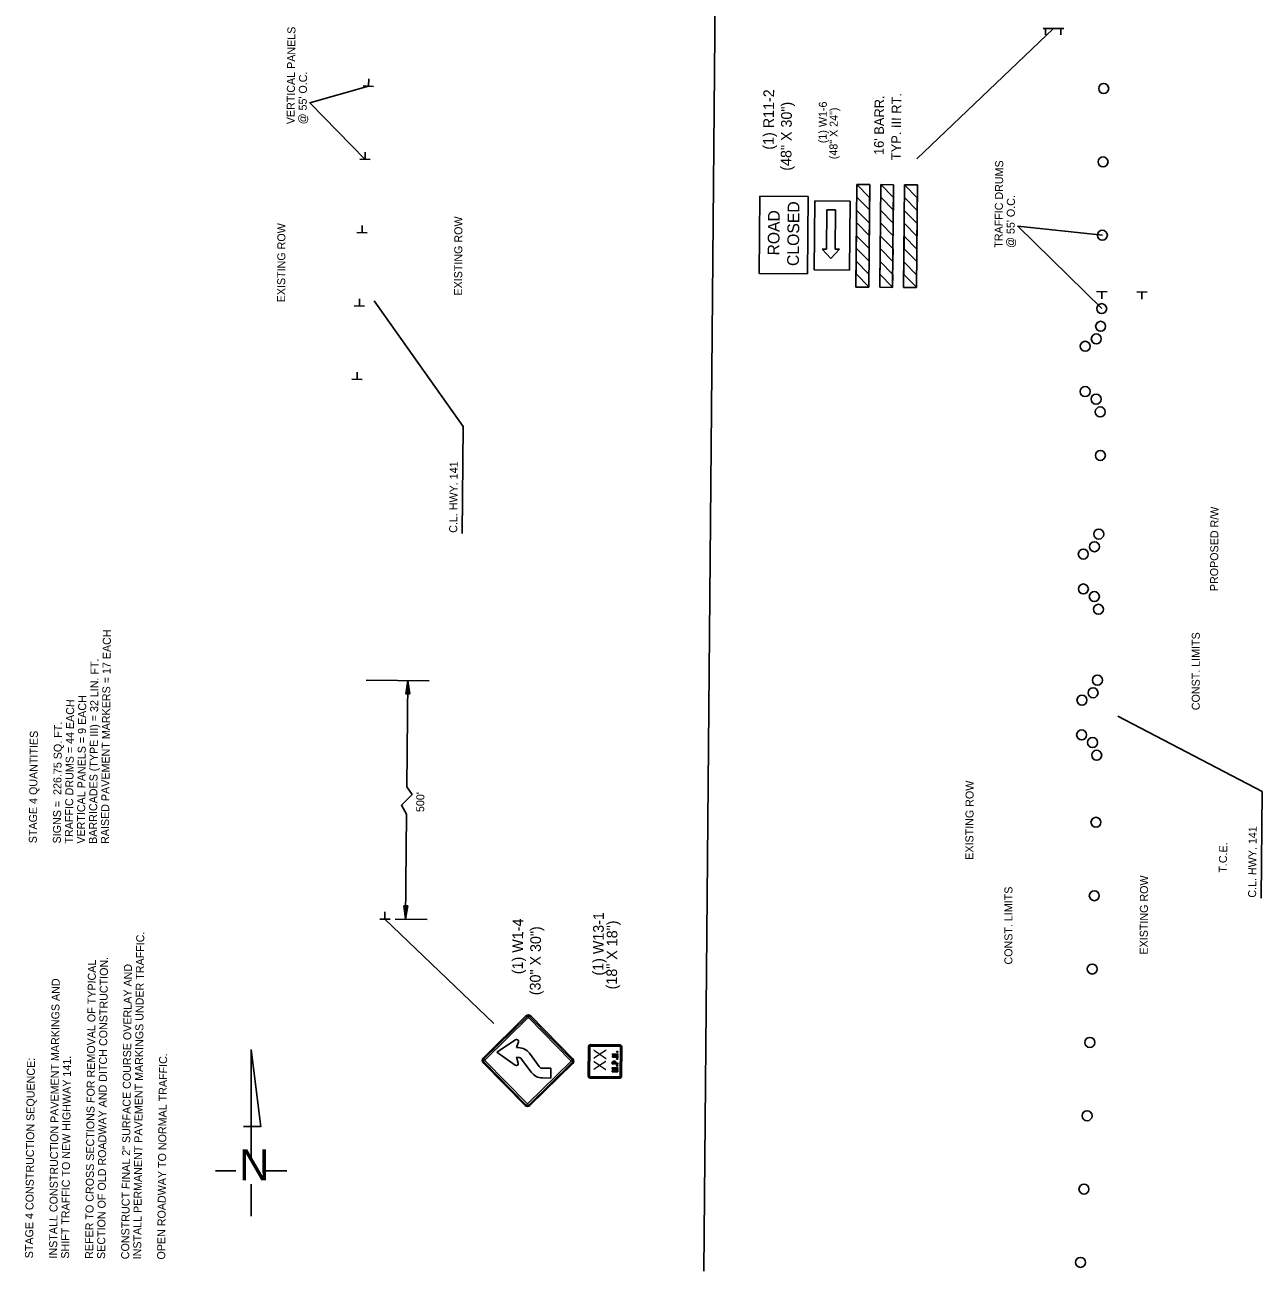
# Model space of a CAD drawing. Extents: x 1770269 to 1771406, y 724066 to 730989.
# Drawn here: x 1770269 to 1771196, y 729408 to 730342 of the extents above; entities that cross this region are included whole.
import ezdxf

# ---------------------------------------------------------------- set-up
doc = ezdxf.new("R2010")
doc.units = 0
for name, color, linetype in [('Default', 7, 'Continuous'), ('E_Existing ROW', 7, 'Continuous'), ('R_Border Notes', 7, 'Continuous'), ('R_Border PE', 7, 'Continuous'), ('R_Dimension', 7, 'Continuous'), ('R_Draft', 7, 'Continuous'), ('R_Horz Alg Annot', 7, 'Continuous'), ('R_MOT', 7, 'Continuous'), ('R_ROW Annot', 7, 'Continuous'), ('R_Temp Easement Annot', 7, 'Continuous'), ('Roadway-Signs', 7, 'Continuous')]:
    doc.layers.add(name, color=color, linetype=linetype)

msp = doc.modelspace()

# ---------------------------------------------------------------- linework, layer by layer
at = {"layer": 'Default'}
for p, q in [((1770529.9, 730295.6), (1770522.08, 730295.95)), ((1770526.02, 730295.89), (1770526.26, 730301.23)), ((1770527.4, 730240.68), (1770519.58, 730240.99)), ((1770523.52, 730240.95), (1770523.73, 730246.28)), ((1770525.16, 730185.74), (1770517.34, 730186.01)), ((1770521.28, 730185.99), (1770521.46, 730191.33)), ((1770519.3, 730131.03), (1770519.46, 730136.37)), ((1771079.54, 730141.71), (1771071.71, 730141.78)), ((1771075.64, 730141.63), (1771075.6, 730136.29)), ((1771109.53, 730141.44), (1771101.71, 730141.51)), ((1771105.64, 730141.36), (1771105.59, 730136.02)), ((1770523.19, 730130.8), (1770515.37, 730131.03)), ((1770530.42, 730134.89), (1770597.04, 730040.58)), ((1770517.59, 730076.06), (1770517.72, 730081.39)), ((1770521.48, 730075.84), (1770513.66, 730076.04)), ((1770596.31, 729960.58), (1770597.04, 730040.58)), ((1771087.61, 729823.56), (1771195.68, 729767.17)), ((1771194.95, 729687.17), (1771195.68, 729767.17)), ((1770542.3, 729671.47), (1770534.48, 729671.54)), ((1770538.41, 729671.62), (1770538.46, 729676.96))]:
    msp.add_line(p, q, dxfattribs=at)
at = {"layer": 'R_Border Notes'}
msp.add_line((1770791.68, 730988.54), (1770777.32, 729407.71), dxfattribs=at)
at = {"layer": 'R_Border PE'}
for p, q in [((1770936.97, 730241.15), (1771039.33, 730338.97)), ((1770619.95, 729593.31), (1770538.39, 729671.51))]:
    msp.add_line(p, q, dxfattribs=at)
at = {"layer": 'R_Dimension'}
for p, q in [((1770524.31, 729850.6), (1770571.58, 729850.17)), ((1770553.99, 729840.33), (1770555.58, 729850.32)), ((1770554.24, 729840.33), (1770555.57, 729848.65)), ((1770554.5, 729840.33), (1770555.55, 729846.93)), ((1770554.86, 729770.7), (1770555.58, 729850.32)), ((1770556.49, 729840.31), (1770555.55, 729846.93)), ((1770556.74, 729840.3), (1770555.57, 729848.65)), ((1770556.99, 729840.3), (1770555.58, 729850.32)), ((1770553.99, 729840.33), (1770556.99, 729840.3)), ((1770554.75, 729840.32), (1770555.54, 729845.26)), ((1770555.01, 729840.32), (1770555.52, 729843.57)), ((1770555.26, 729840.32), (1770555.51, 729841.9)), ((1770555.73, 729840.31), (1770555.51, 729841.9)), ((1770555.98, 729840.31), (1770555.52, 729843.57)), ((1770556.24, 729840.31), (1770555.54, 729845.26)), ((1770553.95, 729671.37), (1770554.67, 729750.19)), ((1770552.54, 729681.38), (1770553.95, 729671.37)), ((1770555.54, 729681.35), (1770552.54, 729681.38)), ((1770552.79, 729681.38), (1770553.97, 729673.04)), ((1770553.05, 729681.38), (1770553.98, 729674.76)), ((1770553.3, 729681.37), (1770554, 729676.42)), ((1770553.55, 729681.37), (1770554.01, 729678.12)), ((1770553.81, 729681.37), (1770554.03, 729679.79)), ((1770555.54, 729681.35), (1770553.95, 729671.37)), ((1770555.29, 729681.35), (1770553.97, 729673.04)), ((1770555.04, 729681.36), (1770553.98, 729674.76)), ((1770554.79, 729681.36), (1770554, 729676.42)), ((1770554.53, 729681.36), (1770554.01, 729678.12)), ((1770554.28, 729681.36), (1770554.03, 729679.79)), ((1770546.09, 729671.44), (1770569.95, 729671.22))]:
    msp.add_line(p, q, dxfattribs=at)
for points in [[(1770523.49, 730240.83), (1770482.16, 730283.36), (1770525.99, 730295.78)], [(1771075.51, 730128.99), (1771012.61, 730190.77), (1771076.01, 730183.99)], [(1770554.67, 729750.19), (1770550.79, 729756.86), (1770558.74, 729764.82), (1770554.86, 729770.7)]]:
    msp.add_lwpolyline(points, dxfattribs=at)
at = {"layer": 'R_Draft'}
for p, q in [((1770438.1, 729573.88), (1770445.39, 729515.69)), ((1770438.1, 729492.53), (1770438.1, 729573.88)), ((1770432.46, 729516.12), (1770445.39, 729516.12)), ((1770411.35, 729482.94), (1770426.78, 729482.94)), ((1770448.38, 729482.94), (1770464.86, 729482.94)), ((1770438.1, 729448.89), (1770438.1, 729472.81))]:
    msp.add_line(p, q, dxfattribs=at)
at = {"layer": 'R_MOT'}
for p, q in [((1771031.54, 730339.04), (1771047.12, 730338.9)), ((1771033.5, 730339.02), (1771033.46, 730334.31)), ((1771044.99, 730338.92), (1771044.95, 730334.2)), ((1770891.36, 730145.21), (1770892.05, 730222.09)), ((1770901.71, 730222), (1770892.05, 730222.09)), ((1770901.01, 730145.13), (1770901.71, 730222)), ((1770901.68, 730221.94), (1770901.62, 730222)), ((1770909.25, 730145.05), (1770909.95, 730221.92)), ((1770919.57, 730221.84), (1770909.95, 730221.92)), ((1770919.57, 730221.84), (1770909.95, 730221.92)), ((1770918.87, 730144.96), (1770919.57, 730221.84)), ((1770927.08, 730144.89), (1770927.78, 730221.76)), ((1770937.41, 730221.67), (1770927.78, 730221.76)), ((1770936.71, 730144.8), (1770937.41, 730221.67)), ((1770818.88, 730155.33), (1770819.41, 730213.29)), ((1770855.62, 730212.96), (1770819.41, 730213.29)), ((1770855.09, 730155), (1770855.62, 730212.96)), ((1770869.57, 730203.05), (1770869.3, 730173.66)), ((1770876.11, 730202.99), (1770869.57, 730203.05)), ((1770876.11, 730202.99), (1770875.85, 730173.6)), ((1770869.3, 730173.66), (1770866.03, 730173.69)), ((1770872.51, 730166.45), (1770866.03, 730173.69)), ((1770879.12, 730173.57), (1770872.51, 730166.45)), ((1770875.85, 730173.6), (1770879.12, 730173.57)), ((1770855.09, 730155), (1770818.88, 730155.33)), ((1770901.01, 730145.13), (1770891.36, 730145.21)), ((1770918.87, 730144.96), (1770909.25, 730145.05)), ((1770936.71, 730144.8), (1770927.08, 730144.89))]:
    msp.add_line(p, q, dxfattribs=at)
for points in [[(1770892.05, 730222.09), (1770892, 730212.64), (1770901.51, 730202.95), (1770901.59, 730212.38)], [(1770909.95, 730221.92), (1770909.89, 730212.47), (1770919.4, 730202.79), (1770919.48, 730212.21)], [(1770927.78, 730221.76), (1770927.73, 730212.31), (1770937.23, 730202.63), (1770937.32, 730212.05)], [(1770886.47, 730157.93), (1770886.94, 730209.46), (1770860.59, 730209.7), (1770860.12, 730158.17)], [(1770891.88, 730202.88), (1770891.82, 730193.43), (1770901.33, 730183.74), (1770901.42, 730193.17)], [(1770909.77, 730202.72), (1770909.72, 730193.26), (1770919.22, 730183.58), (1770919.31, 730193)], [(1770927.61, 730202.55), (1770927.55, 730193.1), (1770937.06, 730183.42), (1770937.14, 730192.84)], [(1770891.71, 730183.67), (1770891.65, 730174.22), (1770901.16, 730164.54), (1770901.24, 730173.96)], [(1770909.6, 730183.51), (1770909.54, 730174.06), (1770919.05, 730164.37), (1770919.13, 730173.8)], [(1770927.43, 730183.34), (1770927.38, 730173.89), (1770936.88, 730164.21), (1770936.97, 730173.63)], [(1770891.53, 730164.46), (1770891.47, 730155.01), (1770900.98, 730145.33), (1770901.07, 730154.75)], [(1770909.42, 730164.3), (1770909.37, 730154.85), (1770918.87, 730145.16), (1770918.96, 730154.59)], [(1770927.26, 730164.14), (1770927.2, 730154.68), (1770936.71, 730145), (1770936.8, 730154.42)]]:
    msp.add_lwpolyline(points, close=True, dxfattribs=at)
for centre in [(1771077.01, 730293.99), (1771076.51, 730238.99), (1771076.01, 730183.99), (1771075.51, 730128.99), (1771074.72, 730115.75), (1771071.47, 730106.29), (1771063.15, 730100.75), (1771063.11, 730066.82), (1771071.33, 730061.13), (1771074.41, 730051.61), (1771074.51, 730019), (1771073.3, 729960.05), (1771070.06, 729950.59), (1771061.73, 729945.05), (1771061.77, 729918.89), (1771069.99, 729913.2), (1771073.06, 729903.68), (1771072.28, 729850.56), (1771060.71, 729835.56), (1771069.03, 729841.1), (1771060.47, 729809.53), (1771068.69, 729803.84), (1771071.77, 729794.32), (1771071.23, 729744.02), (1771069.96, 729689.03), (1771068.42, 729634.06), (1771066.61, 729579.08), (1771064.55, 729524.12), (1771062.22, 729469.17), (1771059.62, 729414.23)]:
    msp.add_circle(centre, 3.75, dxfattribs=at)
at = {"layer": 'Roadway-Signs'}
for p, q in [((1770644.12, 729598.92), (1770612.01, 729567.39)), ((1770644.7, 729598.33), (1770612.6, 729566.8)), ((1770645.58, 729597.44), (1770613.47, 729565.91)), ((1770677.7, 729565.32), (1770646.17, 729597.43)), ((1770678.59, 729566.2), (1770647.06, 729598.31)), ((1770679.18, 729566.78), (1770647.65, 729598.89)), ((1770622.2, 729571.68), (1770636.26, 729581.09)), ((1770638.45, 729579.42), (1770637.05, 729575.19)), ((1770692.5, 729576.35), (1770714.38, 729576.15)), ((1770692.51, 729577.39), (1770714.39, 729577.2)), ((1770692.51, 729577), (1770714.38, 729576.8)), ((1770636.08, 729562.01), (1770622.2, 729571.68)), ((1770638.31, 729567.89), (1770636.99, 729567.9)), ((1770636.99, 729567.9), (1770638.31, 729563.64)), ((1770637.05, 729575.19), (1770638.38, 729575.18)), ((1770648.11, 729556.7), (1770640.8, 729566.61)), ((1770646.67, 729570.94), (1770653.98, 729561.02)), ((1770690.74, 729553.97), (1770690.94, 729575.85)), ((1770691.13, 729553.97), (1770691.33, 729575.84)), ((1770691.78, 729553.96), (1770691.98, 729575.84)), ((1770714.89, 729575.63), (1770714.7, 729553.75)), ((1770715.55, 729575.62), (1770715.35, 729553.75)), ((1770715.94, 729575.62), (1770715.74, 729553.74)), ((1770611.98, 729563.86), (1770643.51, 729531.75)), ((1770612.58, 729564.44), (1770644.1, 729532.33)), ((1770613.47, 729565.32), (1770645, 729533.21)), ((1770645.58, 729565.32), (1770645.58, 729565.32)), ((1770645.59, 729533.2), (1770677.69, 729564.73)), ((1770646.46, 729532.31), (1770678.57, 729563.84)), ((1770647.04, 729531.72), (1770679.15, 729563.25)), ((1770656.47, 729559.75), (1770662.72, 729559.7)), ((1770662.72, 729559.7), (1770662.65, 729552.4)), ((1770662.65, 729552.4), (1770656.4, 729552.46)), ((1770714.16, 729552.59), (1770692.29, 729552.79)), ((1770714.16, 729552.2), (1770692.29, 729552.39)), ((1770714.17, 729553.24), (1770692.3, 729553.44))]:
    msp.add_line(p, q, dxfattribs=at)
for points in [[(1770708.84, 729568.02), (1770713, 729567.98), (1770713.01, 729568.6), (1770711.17, 729568.62), (1770711.18, 729569.74), (1770713.02, 729569.72), (1770713.02, 729570.35), (1770708.86, 729570.38), (1770708.85, 729569.76), (1770710.46, 729569.75), (1770710.45, 729568.62), (1770708.84, 729568.64), (1770708.84, 729568.02)], [(1770712.82, 729566.49), (1770712.79, 729566.47), (1770712.76, 729566.44), (1770712.73, 729566.42), (1770712.63, 729566.4), (1770712.56, 729566.4), (1770712.5, 729566.4), (1770712.43, 729566.4), (1770712.33, 729566.42), (1770712.27, 729566.45), (1770712.17, 729566.49), (1770712.14, 729566.52), (1770712.1, 729566.54), (1770712.07, 729566.59), (1770712.04, 729566.63), (1770712.01, 729566.73), (1770712.04, 729566.82), (1770712.07, 729566.89), (1770712.14, 729566.93), (1770712.24, 729567), (1770712.3, 729567.02), (1770712.47, 729567.04), (1770712.53, 729567.04), (1770712.67, 729567.02), (1770712.8, 729566.97), (1770712.89, 729566.92), (1770712.96, 729566.85), (1770712.99, 729566.81), (1770712.99, 729566.74), (1770712.99, 729566.67), (1770712.96, 729566.6), (1770712.89, 729566.53), (1770712.82, 729566.49)], [(1770712.87, 729571.75), (1770712.84, 729571.72), (1770712.81, 729571.7), (1770712.77, 729571.68), (1770712.67, 729571.66), (1770712.61, 729571.66), (1770712.54, 729571.66), (1770712.48, 729571.66), (1770712.38, 729571.68), (1770712.31, 729571.71), (1770712.22, 729571.75), (1770712.18, 729571.78), (1770712.15, 729571.8), (1770712.12, 729571.85), (1770712.09, 729571.89), (1770712.05, 729571.98), (1770712.09, 729572.08), (1770712.12, 729572.14), (1770712.19, 729572.19), (1770712.29, 729572.26), (1770712.35, 729572.28), (1770712.52, 729572.3), (1770712.58, 729572.3), (1770712.71, 729572.28), (1770712.84, 729572.23), (1770712.94, 729572.18), (1770713.01, 729572.11), (1770713.04, 729572.07), (1770713.04, 729572), (1770713.04, 729571.93), (1770713, 729571.86), (1770712.94, 729571.79), (1770712.87, 729571.75)], [(1770713, 729567.98), (1770713.01, 729568.6)], [(1770708.74, 729557.13), (1770712.9, 729557.09), (1770712.91, 729557.67), (1770710.02, 729557.69), (1770709.76, 729557.67), (1770709.96, 729557.72), (1770712.91, 729558.27), (1770712.92, 729558.86), (1770709.97, 729559.46), (1770709.78, 729559.51), (1770710.04, 729559.49), (1770712.93, 729559.46), (1770712.93, 729560.03), (1770708.76, 729560.07), (1770708.76, 729559.2), (1770711.57, 729558.62), (1770711.93, 729558.57), (1770711.57, 729558.53), (1770708.75, 729558), (1770708.74, 729557.13)], [(1770708.8, 729564.18), (1770708.79, 729562.92), (1770712.96, 729562.88), (1770712.96, 729563.5), (1770711.48, 729563.51), (1770711.49, 729564.16)], [(1770711.49, 729564.16), (1770711.46, 729564.3), (1770711.43, 729564.39), (1770711.4, 729564.46), (1770711.36, 729564.53), (1770711.33, 729564.57), (1770711.3, 729564.62), (1770711.23, 729564.69), (1770711.17, 729564.76), (1770711.1, 729564.8), (1770711.04, 729564.85), (1770710.97, 729564.9), (1770710.87, 729564.94), (1770710.78, 729564.99), (1770710.71, 729565.02), (1770710.65, 729565.04), (1770710.55, 729565.06), (1770710.45, 729565.09), (1770710.29, 729565.11), (1770710.19, 729565.11), (1770710.06, 729565.11), (1770709.89, 729565.09), (1770709.86, 729565.09), (1770709.76, 729565.07), (1770709.66, 729565.05), (1770709.53, 729565), (1770709.43, 729564.96), (1770709.33, 729564.91), (1770709.27, 729564.87), (1770709.2, 729564.82), (1770709.13, 729564.78), (1770709.07, 729564.71), (1770709, 729564.64), (1770708.97, 729564.59), (1770708.94, 729564.55), (1770708.9, 729564.48), (1770708.87, 729564.43), (1770708.83, 729564.32), (1770708.8, 729564.18)], [(1770709.49, 729564.04), (1770709.48, 729563.53), (1770710.76, 729563.52), (1770710.77, 729564.03)], [(1770710.77, 729564.03), (1770710.77, 729564.07), (1770710.74, 729564.17), (1770710.7, 729564.23), (1770710.67, 729564.28), (1770710.61, 729564.35), (1770710.54, 729564.4), (1770710.51, 729564.42), (1770710.41, 729564.47), (1770710.31, 729564.49), (1770710.18, 729564.52), (1770710.12, 729564.52), (1770709.95, 729564.49), (1770709.85, 729564.47), (1770709.75, 729564.43), (1770709.69, 729564.38), (1770709.62, 729564.34), (1770709.59, 729564.29), (1770709.56, 729564.24), (1770709.52, 729564.2), (1770709.49, 729564.08), (1770709.49, 729564.06), (1770709.49, 729564.04)], [(1770712.78, 729561.39), (1770712.75, 729561.37), (1770712.71, 729561.35), (1770712.68, 729561.32), (1770712.58, 729561.3), (1770712.51, 729561.3), (1770712.45, 729561.3), (1770712.38, 729561.3), (1770712.29, 729561.33), (1770712.22, 729561.35), (1770712.12, 729561.4), (1770712.09, 729561.42), (1770712.06, 729561.44), (1770712.02, 729561.49), (1770711.99, 729561.53), (1770711.96, 729561.63), (1770711.99, 729561.72), (1770712.03, 729561.79), (1770712.09, 729561.83), (1770712.19, 729561.9), (1770712.26, 729561.92), (1770712.42, 729561.94), (1770712.49, 729561.94), (1770712.62, 729561.92), (1770712.75, 729561.87), (1770712.85, 729561.83), (1770712.91, 729561.76), (1770712.95, 729561.71), (1770712.94, 729561.64), (1770712.94, 729561.57), (1770712.91, 729561.5), (1770712.84, 729561.44), (1770712.78, 729561.39)]]:
    msp.add_lwpolyline(points, dxfattribs=at)
for centre, radius, start, end in [((1770645.87, 729597.14), 2.5, 44.47959, 134.47959), ((1770645.87, 729597.14), 1.67, 44.47959, 134.47959), ((1770645.87, 729597.14), 0.417, 44.47959, 134.47959), ((1770637.07, 729579.88), 1.46, 341.66714, 123.80356), ((1770692.5, 729575.83), 1.56, 89.47959, 179.47959), ((1770692.5, 729575.83), 1.17, 89.47959, 179.47959), ((1770692.5, 729575.83), 0.521, 89.47959, 179.47959), ((1770714.37, 729575.63), 1.17, 359.47959, 89.47959), ((1770714.37, 729575.63), 0.521, 359.47959, 89.47959), ((1770714.37, 729575.63), 1.56, 359.47959, 89.47959), ((1770613.76, 729565.61), 2.5, 134.47959, 224.47959), ((1770613.76, 729565.61), 1.67, 134.47959, 224.47959), ((1770638.29, 729564.76), 3.13, 36.39805, 89.47959), ((1770638.29, 729564.76), 10.42, 36.39766, 89.47959), ((1770677.4, 729565.03), 2.5, 314.47959, 44.47959), ((1770613.76, 729565.61), 0.417, 134.47959, 224.47959), ((1770636.92, 729563.21), 1.46, 235.15563, 17.29204), ((1770656.5, 729562.88), 3.13, 216.39766, 269.47959), ((1770677.4, 729565.03), 0.417, 314.47959, 44.47959), ((1770677.4, 729565.03), 1.67, 314.47959, 44.47959), ((1770656.5, 729562.88), 10.42, 216.39766, 269.47959), ((1770692.3, 729553.96), 1.56, 179.47959, 269.47959), ((1770692.3, 729553.96), 1.17, 179.47959, 269.47959), ((1770692.3, 729553.96), 0.521, 179.47959, 269.47959), ((1770714.17, 729553.76), 1.17, 269.47959, 359.47959), ((1770714.17, 729553.76), 1.56, 269.47959, 359.47959), ((1770714.17, 729553.76), 0.521, 269.47959, 359.47959), ((1770645.29, 729533.5), 2.5, 224.47959, 314.47959), ((1770645.29, 729533.5), 1.67, 224.47959, 314.47959), ((1770645.29, 729533.5), 0.417, 224.47959, 314.47959)]:
    msp.add_arc(centre, radius, start, end, dxfattribs=at)

# ---------------------------------------------------------------- texts
at = {"layer": 'E_Existing ROW'}
for p in [(1770463.63, 730133.71), (1770596.24, 730138.79), (1770979.32, 729715.96), (1771109.99, 729644.93)]:
    msp.add_text('EXISTING ROW', height=6, rotation=89.76484, dxfattribs=at).set_placement(p)
at = {"layer": 'R_Dimension'}
for s, rotation, p in [('VERTICAL PANELS', 89.47959, (1770470.71, 730267.18)), ("@ 55' O.C.", 89.47959, (1770479.71, 730267.1)), ('TRAFFIC DRUMS', 89.47959, (1771001.16, 730174.59)), ("@ 55' O.C.", 89.47959, (1771010.16, 730174.51)), ('CONST. LIMITS', 89.97069, (1771148.97, 729828.05)), ("500'", 89.48163, (1770567.83, 729751.7)), ('CONST. LIMITS', 89.97069, (1771008.6, 729637.44))]:
    msp.add_text(s, height=6, rotation=rotation, dxfattribs=at).set_placement(p)
at = {"layer": 'R_Draft'}
for s, p in [('RAISED PAVEMENT MARKERS = 17 EACH', (1770331.56, 729727.82)), ('BARRICADES (TYPE III) = 32 LIN. FT.', (1770322.56, 729727.9)), ('VERTICAL PANELS = 9 EACH', (1770313.56, 729727.99)), ('TRAFFIC DRUMS = 44 EACH', (1770304.56, 729728.08)), ('STAGE 4 QUANTITIES', (1770277.56, 729728.34)), ('SIGNS =  226.75 SQ. FT.', (1770295.56, 729728.17)), ('INSTALL PERMANENT PAVEMENT MARKINGS UNDER TRAFFIC.', (1770355.73, 729416.48)), ('SECTION OF OLD ROADWAY AND DITCH CONSTRUCTION.', (1770328.73, 729416.74)), ('REFER TO CROSS SECTIONS FOR REMOVAL OF TYPICAL ', (1770319.73, 729416.83)), ('CONSTRUCT FINAL 2" SURFACE COURSE OVERLAY AND', (1770346.73, 729416.57)), ('INSTALL CONSTRUCTION PAVEMENT MARKINGS AND', (1770292.73, 729417.09)), ('STAGE 4 CONSTRUCTION SEQUENCE:', (1770274.73, 729417.27)), ('SHIFT TRAFFIC TO NEW HIGHWAY 141.', (1770301.73, 729417.01)), ('OPEN ROADWAY TO NORMAL TRAFFIC. ', (1770373.73, 729416.31))]:
    msp.add_text(s, height=6, rotation=89.44353, dxfattribs=at).set_placement(p)
msp.add_text('N', height=23.27, dxfattribs=at).set_placement((1770429.28, 729475.77))
at = {"layer": 'R_Horz Alg Annot'}
for p in [(1770592.55, 729960.95), (1771191.19, 729687.54)]:
    msp.add_text('C.L. HWY. 141', height=6, rotation=89.47756, dxfattribs=at).set_placement(p)
at = {"layer": 'R_MOT'}
for s, height, p in [('(1) R11-2', 8.004, (1770829.69, 730248.09)), ("16' BARR.", 7.204, (1770912.13, 730244.09)), ('TYP. III RT.', 7.2036, (1770924.96, 730240.23)), ('(48" X 30")', 8.004, (1770842.93, 730232.34)), ('(1) W1-6', 6, (1770869.31, 730252.97)), ('(48" X 24")', 6, (1770877.45, 730240.97)), ('ROAD', 8.774, (1770833.98, 730168.83)), ('CLOSED', 8.817, (1770848.6, 730160.91)), ('(1) W1-4', 8.004, (1770641.73, 729630.18)), ('(1) W13-1', 8, (1770702.09, 729629.14)), ('(18" X 18")', 8, (1770712.25, 729618.78)), ('(30" X 30")', 8.004, (1770654.97, 729614.43))]:
    msp.add_text(s, height=height, rotation=89.47959, dxfattribs=at).set_placement(p)
at = {"layer": 'R_ROW Annot'}
msp.add_text('PROPOSED R/W', height=6, rotation=89.64311, dxfattribs=at).set_placement((1771162.66, 729917.27))
at = {"layer": 'R_Temp Easement Annot'}
msp.add_text('T.C.E.', height=6, rotation=88.47132, dxfattribs=at).set_placement((1771169.1, 729706.23))
at = {"layer": 'Roadway-Signs'}
msp.add_text('XX', height=9.375, rotation=89.47959, dxfattribs=at).set_placement((1770704.12, 729557.58))

doc.saveas('drawing.dxf')
